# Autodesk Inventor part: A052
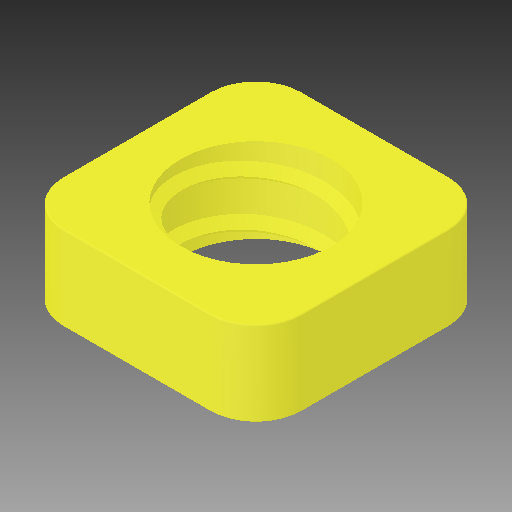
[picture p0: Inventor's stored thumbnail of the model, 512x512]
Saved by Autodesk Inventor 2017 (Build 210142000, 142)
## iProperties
Part Number: A052
Material: Générique
Document SubType Name: Modeling
Designer: ficho
Density: 1 g/cm^3
Appearance: Par défaut
Author: ficho
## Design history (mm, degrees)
feature "Solid1"
node "Solide1"
